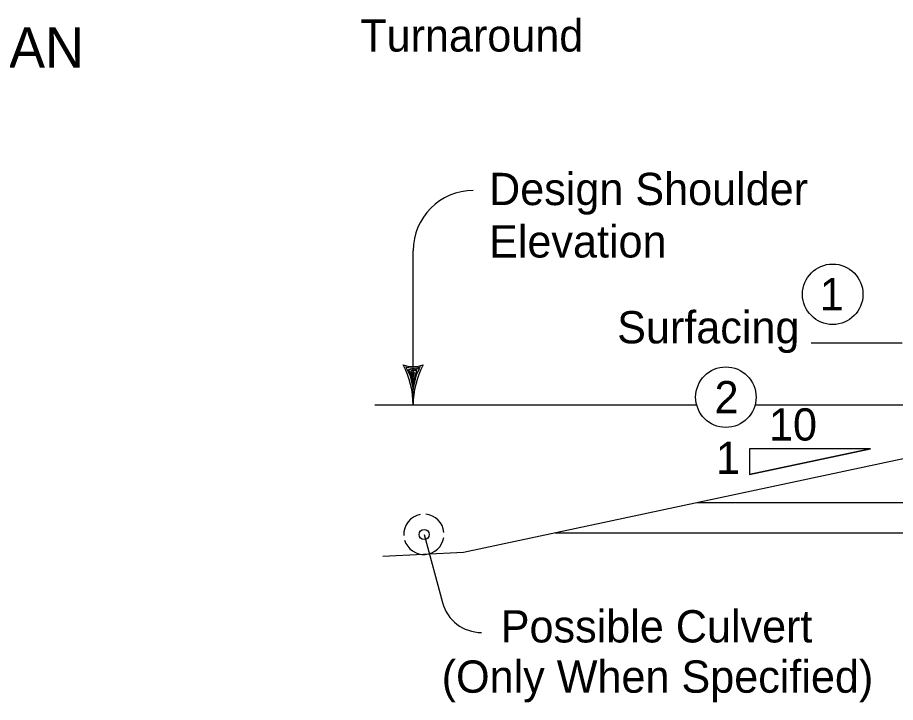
# Model space of a CAD drawing. Extents: x -772 to 772, y -957 to 657.
# Drawn here: x -404.8 to 30.5, y -49.7 to 290 of the extents above; entities that cross this region are included whole.
import ezdxf

# ---------------------------------------------------------------- set-up
doc = ezdxf.new("R2010")
doc.units = 0
for name, color, linetype in [('dsnStdNote', 7, 'Continuous'), ('Level 2', 7, 'Continuous'), ('Level 3', 7, 'Continuous'), ('Level 4', 7, 'Continuous')]:
    doc.layers.add(name, color=color, linetype=linetype)

msp = doc.modelspace()

# ---------------------------------------------------------------- linework, layer by layer
at = {"layer": 'dsnStdNote'}
for centre in [(-0.56, 152.72), (-53.54, 101.71)]:
    msp.add_circle(centre, 15, dxfattribs=at)
at = {"layer": 'Level 2'}
for p, q in [((-208.63, 97.88), (-208.63, 174.34)), ((33.91, 128.48), (-11.18, 128.48)), ((-208.63, 97.69), (-208.63, 116.91)), ((-67.99, 97.69), (-227.65, 97.69)), ((166.28, 97.69), (-39.09, 97.69)), ((18.19, 76.11), (-41.81, 76.11)), ((-41.81, 76.11), (-41.81, 63.33)), ((18.19, 76.11), (-41.81, 63.33)), ((46.28, 73.69), (-183.72, 24.69)), ((-203.12, 33.62), (-194.06, -0.19)), ((-183.72, 24.69), (-223.72, 22.69))]:
    msp.add_line(p, q, dxfattribs=at)
msp.add_lwpolyline([(-205.07, 116.52), (-208.65, 115.8), (-212.26, 116.55), (-210.18, 112.25), (-208.65, 105.43), (-206.94, 112.76), (-205.53, 115.92), (-208.65, 115.14), (-210.96, 115.44), (-209.61, 112.61), (-208.65, 108.83), (-207.48, 112.85), (-206.76, 114.96), (-209.82, 114.57), (-208.65, 111.77), (-207.96, 113.97), (-209.01, 114), (-208.68, 112.97)], dxfattribs=at)
msp.add_circle((-203.14, 33.6), 2.5, dxfattribs=at)
for centre, radius, start, end in [((-178.82, 174.34), 29.81, 90, 180), ((-208.63, 133.33), 16.42, 252.2666, 287.7333), ((-251.13, 97.69), 42.5, 0, 28.0725), ((-166.13, 97.69), 42.5, 151.9275, 180), ((-203.31, 33.68), 10, 5.3537, 84.583), ((-203.31, 33.68), 10, 100.2762, 183.1548), ((-203.31, 33.68), 10, 197.1103, 350.857), ((-174.74, 4.99), 20, 194.9986, 269.9828)]:
    msp.add_arc(centre, radius, start, end, dxfattribs=at)
at = {"layer": 'Level 4'}
for p, q in [((-67.78, 49.39), (400.35, 49.39)), ((-138.19, 34.39), (470.75, 34.39))]:
    msp.add_line(p, q, dxfattribs=at)
msp.add_lwpolyline([(18.19, 76.11), (-41.81, 76.11), (-41.81, 63.33)], close=True, dxfattribs=at)
msp.add_circle((-203.14, 33.6), 2.5, dxfattribs=at)

# ---------------------------------------------------------------- texts
at = {"layer": 'Level 3'}
for s, height, p in [('Turnaround', 16, (-234.87, 273.1)), ('PLAN', 20, (-441.73, 265.1)), ('Design Shoulder', 16, (-170.99, 196.95)), ('Elevation', 16, (-170.99, 170.95)), ('1', 16, (-6.98, 144.75)), ('Surfacing', 16, (-107.46, 128.37)), ('2', 16, (-59.16, 93.71)), ('10', 16, (-32.16, 80.17)), ('1', 16, (-58.47, 63.6)), ('Possible Culvert', 16, (-165.19, -19.95)), ('(Only When Specified)', 16, (-194.48, -44.88))]:
    msp.add_text(s, height=height, dxfattribs=at).set_placement(p)

doc.saveas('drawing.dxf')
